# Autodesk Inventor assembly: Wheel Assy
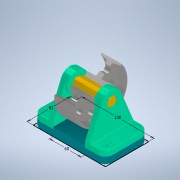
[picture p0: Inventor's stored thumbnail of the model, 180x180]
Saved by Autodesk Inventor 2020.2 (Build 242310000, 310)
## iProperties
Created: 2020-01
Part Number: Wheel Assy
Document SubType Name: Assembly
Designer: thira
Author: thira
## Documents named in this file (5)
- C:\Users\thira\OneDrive\เดสก์ท็อป\INV-01 Intro to Modeling_2020\Wheel Assem Final V1\Wheel Assy.iam
- C:\Users\thira\OneDrive\เดสก์ท็อป\INV-01 Intro to Modeling_2020\Wheel Assem Final V1\Plate V1.ipt
- C:\Users\thira\OneDrive\เดสก์ท็อป\INV-01 Intro to Modeling_2020\Wheel Assem Final V1\Shaft V1.ipt
- C:\Users\thira\OneDrive\เดสก์ท็อป\INV-01 Intro to Modeling_2020\Wheel Assem Final V1\Support Wheel V1.ipt
- C:\Users\thira\OneDrive\เดสก์ท็อป\INV-01 Intro to Modeling_2020\Wheel Assem Final V1\Wheel V1.ipt
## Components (5 placed, 4 different names)
1. Plate V1:1 — Mate:1, Flush:1, Mate:2, Insert:1, Insert:2
2. Shaft V1:1 — Mate:3, Flush:2, Flush:3, Mate:4
3. Support Wheel V1:1 — Mate:1, Flush:1, Mate:2, Mate:3, Flush:2
4. Wheel V1:1 — Flush:3, Mate:4
5. Support Wheel V1:2 — Insert:1, Insert:2
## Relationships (9: Mate 4, Flush 3, Insert 2)
- Mate:1: Plate V1:1 ↔ Support Wheel V1:1
- Flush:1: Plate V1:1 ↔ Support Wheel V1:1
- Mate:2: Plate V1:1 ↔ Support Wheel V1:1
- Insert:1: Plate V1:1 ↔ Support Wheel V1:2
- Insert:2: Plate V1:1 ↔ Support Wheel V1:2
- Mate:3: Shaft V1:1 ↔ Support Wheel V1:1
- Flush:2: Shaft V1:1 ↔ Support Wheel V1:1
- Flush:3: Shaft V1:1 ↔ Wheel V1:1
- Mate:4: Shaft V1:1 ↔ Wheel V1:1
